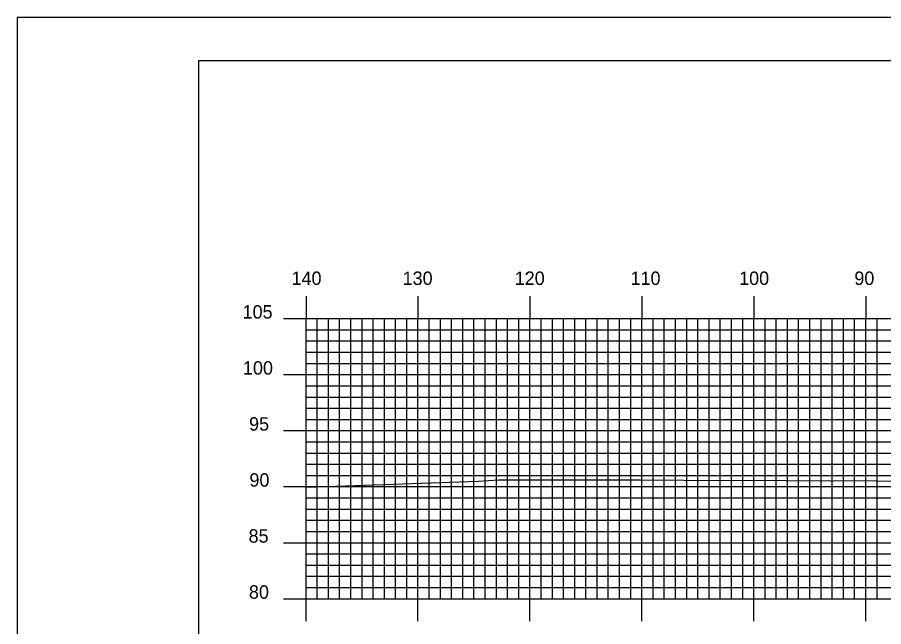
# Model space of a CAD drawing. Extents: x 1763365 to 1763708, y 442591 to 442811.
# Drawn here: x 1763365 to 1763442.4, y 442756.2 to 442810.5 of the extents above; entities that cross this region are included whole.
import ezdxf

# ---------------------------------------------------------------- set-up
doc = ezdxf.new("R2010")
doc.units = 0
for name, color, linetype in [('BORDER', 7, 'Continuous'), ('H_V ANNOTATION', 7, 'Continuous'), ('MAJOR', 7, 'Continuous'), ('MINOR', 7, 'Continuous'), ('PLOT BOUNDARY', 7, 'Continuous'), ('S_Roadway_Centerline', 7, 'Continuous')]:
    doc.layers.add(name, color=color, linetype=linetype)

msp = doc.modelspace()

# ---------------------------------------------------------------- linework, layer by layer
at = {"layer": 'BORDER'}
msp.add_lwpolyline([(1763381.205, 442596.665), (1763701.205, 442596.665), (1763701.205, 442806.665), (1763381.205, 442806.665)], close=True, dxfattribs=at)
at = {"layer": 'MAJOR'}
for p, q in [((1763390.805, 442785.669), (1763390.805, 442783.665)), ((1763400.805, 442785.669), (1763400.805, 442783.665)), ((1763410.805, 442785.669), (1763410.805, 442783.665)), ((1763420.805, 442785.669), (1763420.805, 442783.665)), ((1763430.805, 442785.669), (1763430.805, 442783.665)), ((1763440.805, 442785.669), (1763440.805, 442783.665)), ((1763388.801, 442783.665), (1763390.805, 442783.665)), ((1763390.805, 442783.665), (1763670.805, 442783.665)), ((1763390.805, 442758.665), (1763390.805, 442783.665)), ((1763390.805, 442758.665), (1763390.805, 442783.665)), ((1763390.805, 442783.665), (1763670.805, 442783.665)), ((1763400.805, 442758.665), (1763400.805, 442783.665)), ((1763410.805, 442758.665), (1763410.805, 442783.665)), ((1763420.805, 442758.665), (1763420.805, 442783.665)), ((1763430.805, 442758.665), (1763430.805, 442783.665)), ((1763440.805, 442758.665), (1763440.805, 442783.665)), ((1763388.801, 442778.665), (1763390.805, 442778.665)), ((1763390.805, 442778.665), (1763670.805, 442778.665)), ((1763388.801, 442773.665), (1763390.805, 442773.665)), ((1763390.805, 442773.665), (1763670.805, 442773.665)), ((1763388.801, 442768.665), (1763390.805, 442768.665)), ((1763390.805, 442768.665), (1763670.805, 442768.665)), ((1763388.801, 442763.665), (1763390.805, 442763.665)), ((1763390.805, 442763.665), (1763670.805, 442763.665)), ((1763388.801, 442758.665), (1763390.805, 442758.665)), ((1763390.805, 442758.665), (1763670.805, 442758.665)), ((1763390.805, 442758.665), (1763670.805, 442758.665)), ((1763390.805, 442756.661), (1763390.805, 442758.665)), ((1763400.805, 442756.661), (1763400.805, 442758.665)), ((1763410.805, 442756.661), (1763410.805, 442758.665)), ((1763420.805, 442756.661), (1763420.805, 442758.665)), ((1763430.805, 442756.661), (1763430.805, 442758.665)), ((1763440.805, 442756.661), (1763440.805, 442758.665))]:
    msp.add_line(p, q, dxfattribs=at)
at = {"layer": 'MINOR'}
for p, q in [((1763391.805, 442758.665), (1763391.805, 442783.665)), ((1763392.805, 442758.665), (1763392.805, 442783.665)), ((1763393.805, 442758.665), (1763393.805, 442783.665)), ((1763394.805, 442758.665), (1763394.805, 442783.665)), ((1763395.805, 442758.665), (1763395.805, 442783.665)), ((1763396.805, 442758.665), (1763396.805, 442783.665)), ((1763397.805, 442758.665), (1763397.805, 442783.665)), ((1763398.805, 442758.665), (1763398.805, 442783.665)), ((1763399.805, 442758.665), (1763399.805, 442783.665)), ((1763401.805, 442758.665), (1763401.805, 442783.665)), ((1763402.805, 442758.665), (1763402.805, 442783.665)), ((1763403.805, 442758.665), (1763403.805, 442783.665)), ((1763404.805, 442758.665), (1763404.805, 442783.665)), ((1763405.805, 442758.665), (1763405.805, 442783.665)), ((1763406.805, 442758.665), (1763406.805, 442783.665)), ((1763407.805, 442758.665), (1763407.805, 442783.665)), ((1763408.805, 442758.665), (1763408.805, 442783.665)), ((1763409.805, 442758.665), (1763409.805, 442783.665)), ((1763411.805, 442758.665), (1763411.805, 442783.665)), ((1763412.805, 442758.665), (1763412.805, 442783.665)), ((1763413.805, 442758.665), (1763413.805, 442783.665)), ((1763414.805, 442758.665), (1763414.805, 442783.665)), ((1763415.805, 442758.665), (1763415.805, 442783.665)), ((1763416.805, 442758.665), (1763416.805, 442783.665)), ((1763417.805, 442758.665), (1763417.805, 442783.665)), ((1763418.805, 442758.665), (1763418.805, 442783.665)), ((1763419.805, 442758.665), (1763419.805, 442783.665)), ((1763421.805, 442758.665), (1763421.805, 442783.665)), ((1763422.805, 442758.665), (1763422.805, 442783.665)), ((1763423.805, 442758.665), (1763423.805, 442783.665)), ((1763424.805, 442758.665), (1763424.805, 442783.665)), ((1763425.805, 442758.665), (1763425.805, 442783.665)), ((1763426.805, 442758.665), (1763426.805, 442783.665)), ((1763427.805, 442758.665), (1763427.805, 442783.665)), ((1763428.805, 442758.665), (1763428.805, 442783.665)), ((1763429.805, 442758.665), (1763429.805, 442783.665)), ((1763431.805, 442758.665), (1763431.805, 442783.665)), ((1763432.805, 442758.665), (1763432.805, 442783.665)), ((1763433.805, 442758.665), (1763433.805, 442783.665)), ((1763434.805, 442758.665), (1763434.805, 442783.665)), ((1763435.805, 442758.665), (1763435.805, 442783.665)), ((1763436.805, 442758.665), (1763436.805, 442783.665)), ((1763437.805, 442758.665), (1763437.805, 442783.665)), ((1763438.805, 442758.665), (1763438.805, 442783.665)), ((1763439.805, 442758.665), (1763439.805, 442783.665)), ((1763441.805, 442758.665), (1763441.805, 442783.665)), ((1763390.805, 442782.665), (1763670.805, 442782.665)), ((1763390.805, 442782.665), (1763392.809, 442782.665)), ((1763390.805, 442781.665), (1763670.805, 442781.665)), ((1763390.805, 442781.665), (1763392.809, 442781.665)), ((1763390.805, 442780.665), (1763670.805, 442780.665)), ((1763390.805, 442780.665), (1763392.809, 442780.665)), ((1763390.805, 442779.665), (1763670.805, 442779.665)), ((1763390.805, 442779.665), (1763392.809, 442779.665)), ((1763390.805, 442777.665), (1763670.805, 442777.665)), ((1763390.805, 442777.665), (1763392.809, 442777.665)), ((1763390.805, 442776.665), (1763670.805, 442776.665)), ((1763390.805, 442776.665), (1763392.809, 442776.665)), ((1763390.805, 442775.665), (1763670.805, 442775.665)), ((1763390.805, 442775.665), (1763392.809, 442775.665)), ((1763390.805, 442774.665), (1763670.805, 442774.665)), ((1763390.805, 442774.665), (1763392.809, 442774.665)), ((1763390.805, 442772.665), (1763670.805, 442772.665)), ((1763390.805, 442772.665), (1763392.809, 442772.665)), ((1763390.805, 442771.665), (1763670.805, 442771.665)), ((1763390.805, 442771.665), (1763392.809, 442771.665)), ((1763390.805, 442770.665), (1763670.805, 442770.665)), ((1763390.805, 442770.665), (1763392.809, 442770.665)), ((1763390.805, 442769.665), (1763670.805, 442769.665)), ((1763390.805, 442769.665), (1763392.809, 442769.665)), ((1763390.805, 442767.665), (1763670.805, 442767.665)), ((1763390.805, 442767.665), (1763392.809, 442767.665)), ((1763390.805, 442766.665), (1763670.805, 442766.665)), ((1763390.805, 442766.665), (1763392.809, 442766.665)), ((1763390.805, 442765.665), (1763670.805, 442765.665)), ((1763390.805, 442765.665), (1763392.809, 442765.665)), ((1763390.805, 442764.665), (1763670.805, 442764.665)), ((1763390.805, 442764.665), (1763392.809, 442764.665)), ((1763390.805, 442762.665), (1763670.805, 442762.665)), ((1763390.805, 442762.665), (1763392.809, 442762.665)), ((1763390.805, 442761.665), (1763670.805, 442761.665)), ((1763390.805, 442761.665), (1763392.809, 442761.665)), ((1763390.805, 442760.665), (1763670.805, 442760.665)), ((1763390.805, 442760.665), (1763392.809, 442760.665)), ((1763390.805, 442759.665), (1763670.805, 442759.665)), ((1763390.805, 442759.665), (1763392.809, 442759.665))]:
    msp.add_line(p, q, dxfattribs=at)
at = {"layer": 'PLOT BOUNDARY'}
msp.add_lwpolyline([(1763365.019, 442590.547), (1763705.019, 442590.547), (1763705.019, 442810.547), (1763365.019, 442810.547)], close=True, dxfattribs=at)
at = {"layer": 'S_Roadway_Centerline'}
msp.add_lwpolyline([(1763390.805, 442768.606), (1763395.194, 442768.783), (1763406.185, 442769.164), (1763408.021, 442769.264), (1763411.973, 442769.26), (1763420.653, 442769.287), (1763424.547, 442769.249), (1763433.681, 442769.205), (1763441.718, 442769.181), (1763453.167, 442769.072)], dxfattribs=at)

# ---------------------------------------------------------------- texts
at = {"layer": 'H_V ANNOTATION'}
for s, p in [('140', (1763389.51, 442786.665)), ('130', (1763399.435, 442786.665)), ('120', (1763409.446, 442786.665)), ('110', (1763419.789, 442786.665)), ('100', (1763429.489, 442786.665)), ('90', (1763439.778, 442786.665)), ('105', (1763385.14, 442783.665)), ('100', (1763385.172, 442778.665)), ('95', (1763385.718, 442773.665)), ('90', (1763385.75, 442768.665)), ('85', (1763385.675, 442763.665)), ('80', (1763385.707, 442758.665))]:
    msp.add_text(s, height=1.2, dxfattribs=at).set_placement(p)
at = {"layer": 'MAJOR'}
msp.add_text('-', height=0.012, dxfattribs=at).set_placement((1763390.797, 442758.665))

doc.saveas('drawing.dxf')
